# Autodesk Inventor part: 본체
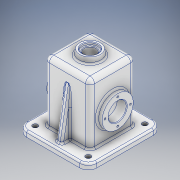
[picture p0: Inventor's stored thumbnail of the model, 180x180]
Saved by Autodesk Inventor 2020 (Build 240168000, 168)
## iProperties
Created: 2022-11
Part Number: 본체
Material: 알루미늄 6061
Document SubType Name: Modeling
Designer: com
Density: 2.7 g/cm^3
Appearance: 알루미늄 - 평지
Mass: 1129.8 g
Surface Area: 1015.53 cm^2
Volume: 418.443 cm^3
Author: com
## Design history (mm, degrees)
sketch "스케치1"
  geometry: L1 (47, 65)-(-47, 65); L2 (-62, 50)-(-62, -50); L3 (-47, -65)-(47, -65); L4 (62, -50)-(62, 50); L5 (62, 65)-(-62, -65); L6 (-62, 65)-(62, -65); A1 r 15 centre (47, -50) between (47, -65) and (62, -50); A2 r 15 centre (-47, -50) between (-62, -50) and (-47, -65); A3 r 15 centre (47, 50) between (62, 50) and (47, 65); A4 r 15 centre (-47, 50) between (-47, 65) and (-62, 50); 1 further point
  constraints: 12 end point, 8 point on circle, 8 point on line, 8 tangent, 4 centre point, 3 equal radius, 2 midpoint, 2 parallel, 1 horizontal, 1 perpendicular
  dimensions: "d0" = 124 distance of L6.end L5.end; "d1" = 130 distance of L5.end L6.start; "d2" = 15 radius of A1
extrude "돌출1" new body sketch "스케치1" distance "d3" = 10; taper "d4" = 0 deg
sketch "스케치2"
  geometry: L1 (-40, -40)-(40, -40); L2 (40, -40)-(40, 40); L3 (40, 40)-(-40, 40); L4 (-40, 40)-(-40, -40); L5 (-40, -40)-(40, 40); L6 (40, -40)-(-40, 40); 1 further point
  constraints: 12 end point, 2 midpoint, 2 parallel, 1 horizontal, 1 perpendicular
  dimensions: "d5" = 80 distance of L3.end L2.end; "d6" = 80 distance of L2.end L1.end
extrude "돌출2" join sketch "스케치2" distance "d7" = 107; taper "d8" = 0 deg
sketch "스케치4"
  geometry: L1 (117, -40)-(117, 40) reference; L2 (117, 0)-(127, 0); L3 (127, 0)-(127, -18.237); L4 (127, -18.237)-(117, -20); L5 (0, 50)-(0, -50) reference; L6 (117, 0)-(117, -20); 1 further point
  constraints: 8 end point, 1 horizontal, 1 midpoint, 1 perpendicular, 1 point on line, 1 vertical
  dimensions: "d10" = 127 distance between parallel lines of L5 L3; "d11" = 20 distance from line of L2 L4.end; "d12" = 100 deg angle of L1 L4
revolve "회전1" sketch "스케치4" stored, may be unused: angle "d13" = 90 deg
sketch "스케치7"
  geometry: L1 (80, 0)-(80, 107) reference; L2 (-10, -10)-(90, -10) reference; C1 r 27.5 at (40, 45); 1 further point
  constraints: 1 centre point
  dimensions: "d18" = 55 diameter of C1; "d19" = 40 distance from line of L1 C1.centre; "d20" = 55 distance from line of L2 C1.centre
extrude "돌출4" join sketch "스케치7" distance "d21" = 9; taper "d22" = 0 deg
sketch "스케치5"
  geometry: L1 (32, -32)-(-32, -32); L2 (-32, -32)-(-32, 32); L3 (-32, 32)-(32, 32); L4 (32, 32)-(32, -32); L5 (32, -32)-(-32, 32); L6 (-32, -32)-(32, 32); 1 further point
  constraints: 12 end point, 2 midpoint, 2 parallel, 1 horizontal, 1 perpendicular
  dimensions: "d14" = 64 distance of L2.end L3.end; "d15" = 64 distance of L1.end L2.end
extrude "돌출3" cut sketch "스케치5" distance "d16" = 109; taper "d17" = 0 deg
sketch "스케치8"
  geometry: C1 r 27.5 at (0, 0) reference; C2 r 16 at (0, 0); 1 further point
  constraints: 1 centre point, 1 coincident
  dimensions: "d24" = 32 diameter of C2
extrude "돌출5" cut sketch "스케치8" extent not by distance; stored distance "d25" = 0; taper "d26" = 0 deg
sketch "스케치9"
  geometry: L1 (10, 50)-(10, 65) reference; L2 (10, 55)-(95.069, 40); L3 (0, 65)-(10, 65) reference; L4 (10, 55)-(10, 40); L5 (10, -50)-(10, 50) reference; L6 (10, 40)-(95.069, 40); L7 (10, 40)-(117, 40) reference; 2 further points
  constraints: 6 end point, 2 point on line, 1 collinear
  dimensions: "d27" = 10 distance from line of L3 L2.start; "d28" = 100 deg angle of L2 L1; "d92" = 85.06923 distance of L4.end L2.end
extrude "돌출6" join sketch "스케치9" stored distance "d29" = 10; taper "d30" = 0 deg
sketch "스케치10"
  geometry: C1 r 18.237 at (0, 0) reference; 2 further points
  constraints: 1 coincident
hole "구멍1" sketch "스케치10" at (0, 0) diameter "d31" = 21; stored, may be unused: countersink angle "d35" = 90 deg, drill point angle "d37" = 118 deg; dims "d32" = 6, "d33" = 28, "d34" = 4, "d36" = 8
sketch "스케치11" dims "d67" = 25
  geometry: C1 r 16 at (0, 0) reference; A1 r 22.5 centre (0, 0) between (0, 22.5) and (-22.5, 0); 3 further points
  constraints: 4 point on circle, 1 centre point, 1 coincident
  dimensions: "d38" = 45 diameter of A1; "d39" = 45 distance of point (0, -22.5) A1.start; "d40" = 45 distance of A1.end point (22.5, 0); "d41" = 22.5 horizontal distance of point (22.5, 0) A1.start; "d42" = 22.5 horizontal distance of A1.end point (0, -22.5)
hole "구멍2" sketch "스케치11" at (0, 22.5), (-22.5, 0), (0, -22.5), (22.5, 0) diameter "d43" = 3.242; stored, may be unused: countersink angle "d47" = 90 deg, drill point angle "d49" = 118 deg; dims "d44" = 8, "d45" = 28, "d46" = 4, "d48" = 10
sketch "스케치13"
  geometry: C1 r 4.5 at (-47, -50); C2 r 4.5 at (47, -50); C3 r 4.5 at (47, 50); C4 r 4.5 at (-47, 50); A1 r 15 centre (-47, -50) between (-62, -50) and (-47, -65) reference; A2 r 15 centre (47, -50) between (47, -65) and (62, -50) reference; A3 r 15 centre (47, 50) between (62, 50) and (47, 65) reference; A4 r 15 centre (-47, 50) between (-47, 65) and (-62, 50) reference; 1 further point
  constraints: 4 centre point, 4 coincident
  dimensions: "d50" = 9 diameter of C1; "d51" = 9 diameter of C2; "d52" = 9 diameter of C3; "d53" = 9 diameter of C4
extrude "돌출7" cut sketch "스케치13" extent not by distance; stored distance "d54" = 0; taper "d55" = 0 deg
sketch "스케치15"
  geometry: L1 (80, 0)-(80, 107) reference; L2 (21.763, 117)-(58.237, 117) reference; L3 (19.389, 95.353)-(60.868, 95.353); L4 (60.868, 95.353)-(60.868, 89.349); L5 (60.868, 89.349)-(19.389, 89.349); L6 (19.389, 89.349)-(19.389, 95.353); L7 (0, 107)-(80, 107) reference; L8 (0, 0)-(0, 107) reference; 2 further points
  constraints: 2 other
  dimensions: "d66" = 40 distance from line of L1 point (40, 92); "d67" = 25 distance from line of L2 point (40, 92); "d70" = 11.64664 distance between parallel lines of L7 L3; "d71" = 19.3891 distance between parallel lines of L8 L6; "d72" = 41.47897 distance of L4.end L5.end; "d73" = 6.00407 distance of L3.end L4.end
feature "엠보싱2" sketch "스케치15" dims "d0" = 124, "d1" = 130, "d2" = 15, "d5" = 80, "d6" = 80, "d68" = 0.5, "d69" = 0
fillet "모깎기3" dims "d74" = 8
fillet "모깎기4" dims "d75" = 3
fillet "모깎기5" dims "d76" = 3
fillet "모깎기6" dims "d77" = 3
fillet "모깎기7" dims "d78" = 3
fillet "모깎기8" dims "d79" = 3
chamfer "모따기1" distance "d80" = 1; stored, may be unused: second distance "d81" = 2, angle "d82" = 45 deg
chamfer "모따기2" distance "d83" = 1; stored, may be unused: second distance "d84" = 2, angle "d85" = 45 deg
chamfer "모따기3" distance "d86" = 1; stored, may be unused: second distance "d87" = 2, angle "d88" = 45 deg
chamfer "모따기4" distance "d89" = 1; stored, may be unused: second distance "d90" = 2, angle "d91" = 45 deg
fillet "모깎기9" dims "d93" = 3
node "솔리드1"
mirror "미러1"
mirror "미러2"
mirror "미러3"
feature "A9D066F2-1C7D-4E18-AEED-F7BC21143FA4" dims "d31" = 21, "d32" = 6, "d33" = 28, "d34" = 4, "d35" = 90 deg, "d36" = 8, "d37" = 118 deg
